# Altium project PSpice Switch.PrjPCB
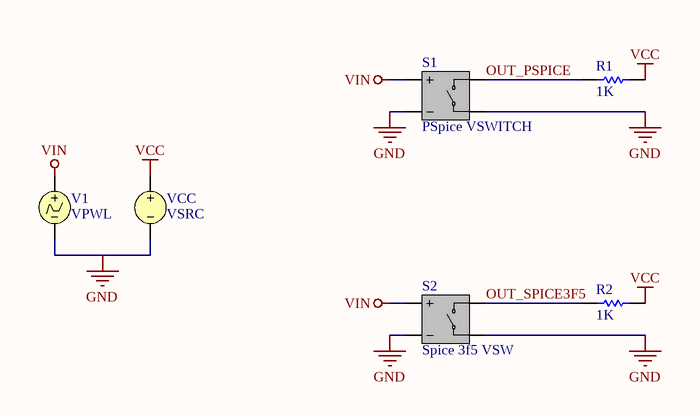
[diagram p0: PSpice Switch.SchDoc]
1 sheet, 6 parts. Net scope: global (net labels, ports and power ports of the same name join across sheets).

## Sheet PSpice Switch.SchDoc: PSpice Switch
size A; DocumentNumber: 1; SheetNumber: 1; SheetTotal: 1

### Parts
R1  value 1K  [AXIAL-0.3]  (hidden comment: Res1)
R2  value 1K  [AXIAL-0.3]  (hidden comment: Res1)
S1  PSpice VSWITCH
S2  Spice 3f5 VSW
V1  VPWL
VCC  VSRC

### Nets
GND: S1.2(N1-) S1.4(N2-) S2.2(N1-) S2.4(N2-) V1.2 VCC.2
VCC: R1.1 R2.1 VCC.1
VIN: S1.1(N1+) S2.1(N1+) V1.1
OUT_PSPICE: R1.2 S1.3(N2+)
OUT_SPICE3F5: R2.2 S2.3(N2+)

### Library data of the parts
R1 R2 = Res1: Resistor
S1 S2 = VSW: Voltage Controlled Switch
V1 = VPWL: Piecewise Linear Voltage Source; Note: PCB Footprint - Not required; Sim Note: To add model file containing time-current pairs of values, enter model location under "General Tab" in "Full Path" box.
VCC = VSRC: Voltage Source; Note: PCB Footprint - Not required; Value: +12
